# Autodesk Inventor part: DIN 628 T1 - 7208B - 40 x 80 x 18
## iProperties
IsCustomPart: 0
Created: 2009-02
Part Number: DIN 628 T1 - 7208B - 40 x 80 x 18
Material: Steel, Mild
Description: Angular Contact Ball Bearing
Document SubType Name: Modeling
Standard: DIN 628 T1
Designer: 904Chiaki
Standards Organization: DIN
Language: en-US
Size Designation: 7208B - 40 x 80 x 18
Categories: <MemberInstance><Categories><Category DisplayName="Shaft Parts" InternalName="7f7aeb1f-a693-4053-b835-cee3144e0d98" Mnemonic="SHFT"><Category DisplayName="Beari
Density: 1 g/cm^3
Author: 904Chiaki
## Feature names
1. Body [Revolution]
2. Fillet1
3. Ball [Revolution]
4. Balls [Circular Pattern]
